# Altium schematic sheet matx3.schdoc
size 594 x 419 mm; Symbol: Drawing-Symbol_A4; @Project Name: Inverted_MAML_6x6; @Page Count: 1; @Update Date: 2026-06-14; @Create Date: 2026-06-14; @Schematic Name: Schematic1; @Page No: 1; @Page Name: P1; Company: EasyEDA.com; Version: V1.0; Page Size: A4; Device: Drawing-Symbol_A4; @Create Time: 14:27:06; @Update Time: 14:27:06; Border: 1; Width: 2338; Height: 1652; Region Start: 1; X Region Count: 6; Y Region Count: 4; Blade Width: 10; Title Block Position: 3
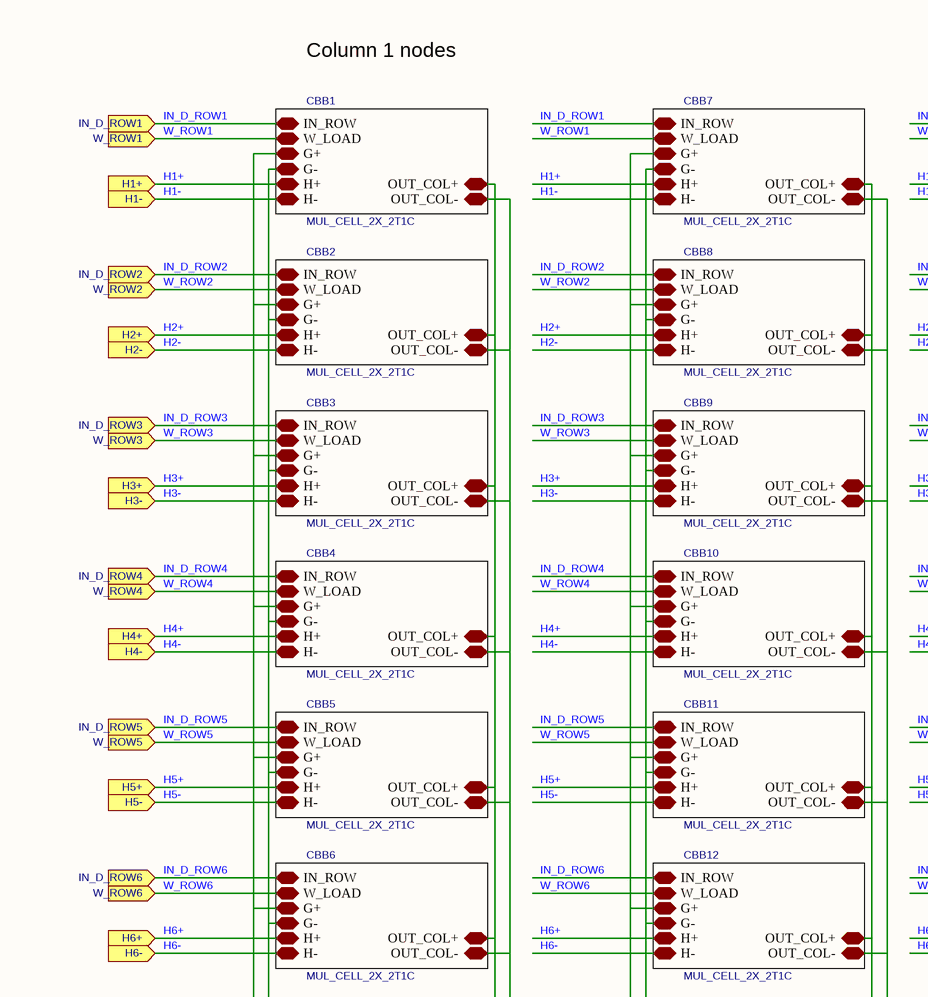
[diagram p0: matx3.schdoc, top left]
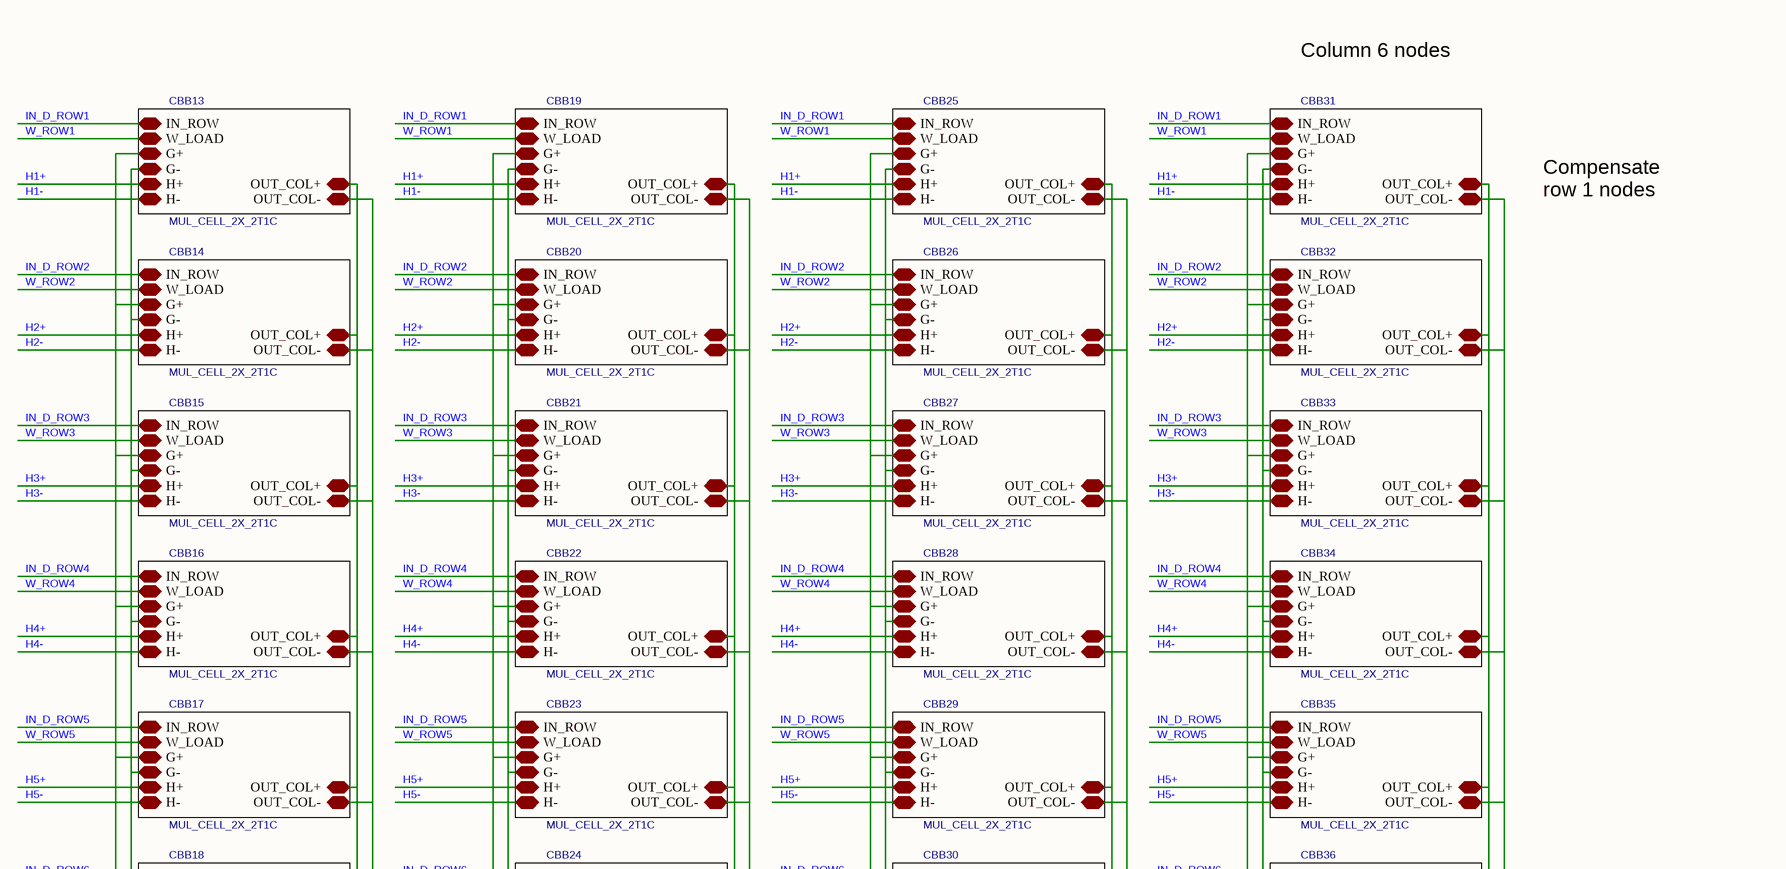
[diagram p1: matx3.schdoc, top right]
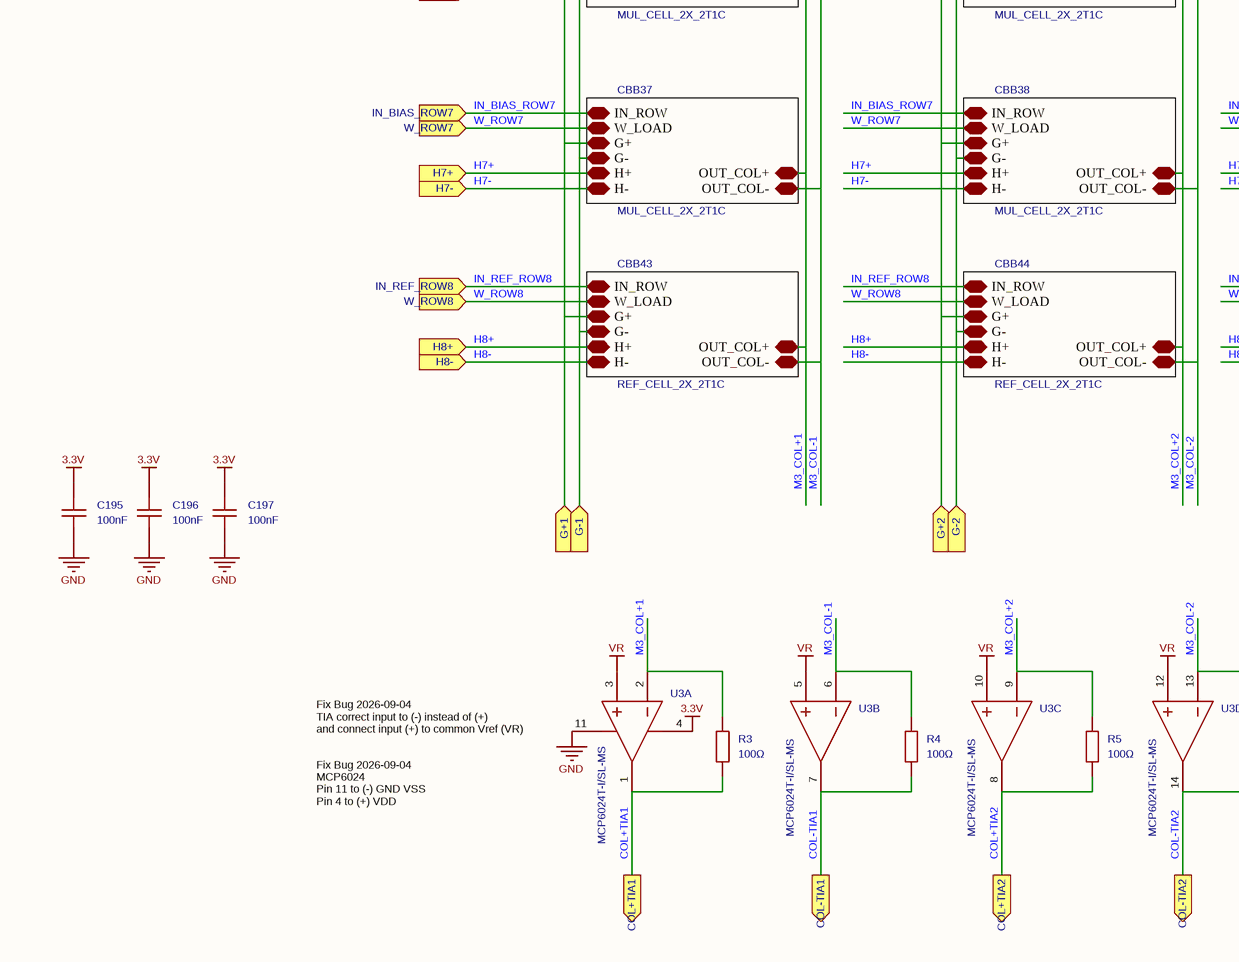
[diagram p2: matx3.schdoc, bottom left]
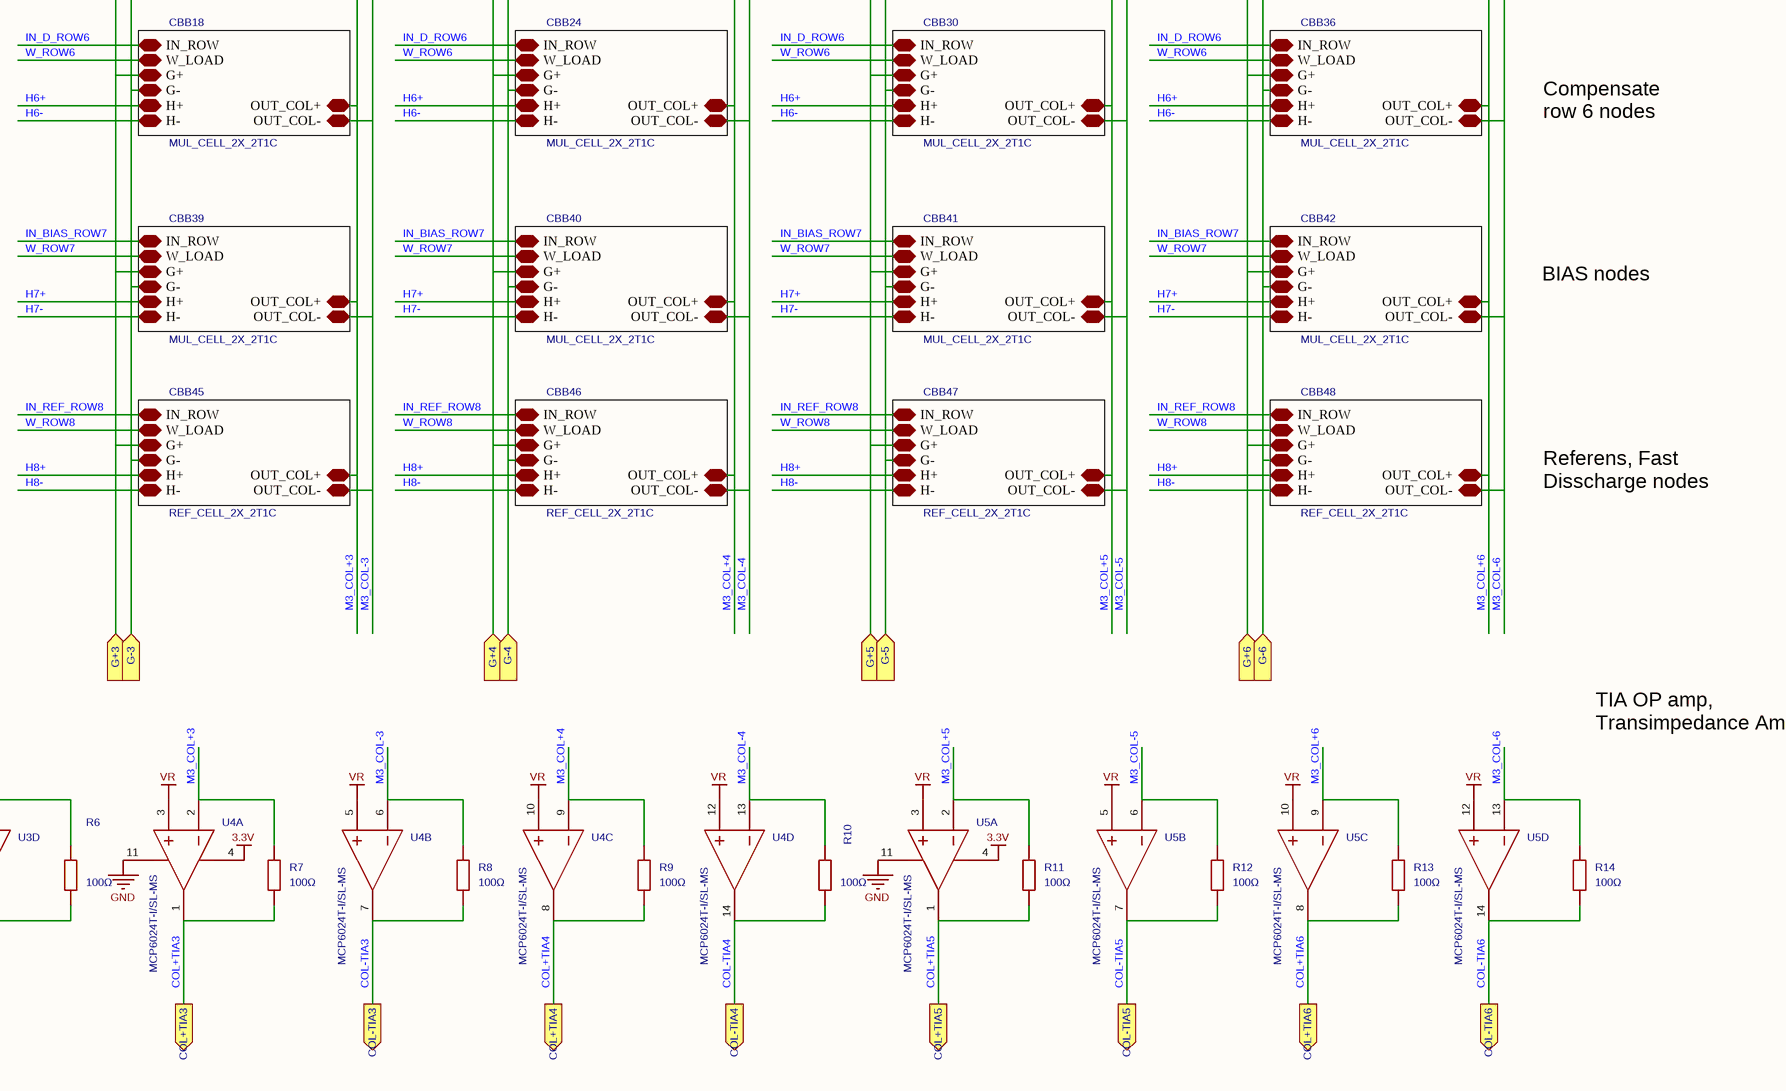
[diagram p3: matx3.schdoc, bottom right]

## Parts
C195  100nF  [C0402]
C196  100nF  [C0402]
C197  100nF  [C0402]
R3  100Ω  [R0402]
R4  100Ω  [R0402]
R5  100Ω  [R0402]
R6  100Ω  [R0402]
R7  100Ω  [R0402]
R8  100Ω  [R0402]
R9  100Ω  [R0402]
R10  100Ω  [R0402]
R11  100Ω  [R0402]
R12  100Ω  [R0402]
R13  100Ω  [R0402]
R14  100Ω  [R0402]
U3  MCP6024T-I/SL-MS  [SOIC-14_L8.7-W3.9-P1.27-LS6.0-BL-1]  (parts A,B,C,D of 4)
U4  MCP6024T-I/SL-MS  [SOIC-14_L8.7-W3.9-P1.27-LS6.0-BL-1]  (parts A,B,C,D of 4)
U5  MCP6024T-I/SL-MS  [SOIC-14_L8.7-W3.9-P1.27-LS6.0-BL-1]  (parts A,B,C,D of 4)

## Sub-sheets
CBB1 = MUL_CELL_2X_2T1C_matrix_3_8_MUL_CELL.schdoc: H+, G+, W_LOAD, IN_ROW, G-, H-, OUT_COL+, OUT_COL-  | Symbol: MUL_CELL_2X_2T1C
CBB2 = MUL_CELL_2X_2T1C_matrix_3_8_MUL_CELL.schdoc: H+, G+, W_LOAD, IN_ROW, G-, H-, OUT_COL+, OUT_COL-  | Symbol: MUL_CELL_2X_2T1C
CBB3 = MUL_CELL_2X_2T1C_matrix_3_8_MUL_CELL.schdoc: H+, G+, W_LOAD, IN_ROW, G-, H-, OUT_COL+, OUT_COL-  | Symbol: MUL_CELL_2X_2T1C
CBB4 = MUL_CELL_2X_2T1C_matrix_3_8_MUL_CELL.schdoc: H+, G+, W_LOAD, IN_ROW, G-, H-, OUT_COL+, OUT_COL-  | Symbol: MUL_CELL_2X_2T1C
CBB5 = MUL_CELL_2X_2T1C_matrix_3_8_MUL_CELL.schdoc: H+, G+, W_LOAD, IN_ROW, G-, H-, OUT_COL+, OUT_COL-  | Symbol: MUL_CELL_2X_2T1C
CBB6 = MUL_CELL_2X_2T1C_matrix_3_8_MUL_CELL.schdoc: H+, G+, W_LOAD, IN_ROW, G-, H-, OUT_COL+, OUT_COL-  | Symbol: MUL_CELL_2X_2T1C
CBB7 = MUL_CELL_2X_2T1C_matrix_3_8_MUL_CELL.schdoc: H+, G+, W_LOAD, IN_ROW, G-, H-, OUT_COL+, OUT_COL-  | Symbol: MUL_CELL_2X_2T1C
CBB8 = MUL_CELL_2X_2T1C_matrix_3_8_MUL_CELL.schdoc: H+, G+, W_LOAD, IN_ROW, G-, H-, OUT_COL+, OUT_COL-  | Symbol: MUL_CELL_2X_2T1C
CBB9 = MUL_CELL_2X_2T1C_matrix_3_8_MUL_CELL.schdoc: H+, G+, W_LOAD, IN_ROW, G-, H-, OUT_COL+, OUT_COL-  | Symbol: MUL_CELL_2X_2T1C
CBB10 = MUL_CELL_2X_2T1C_matrix_3_8_MUL_CELL.schdoc: H+, G+, W_LOAD, IN_ROW, G-, H-, OUT_COL+, OUT_COL-  | Symbol: MUL_CELL_2X_2T1C
CBB11 = MUL_CELL_2X_2T1C_matrix_3_8_MUL_CELL.schdoc: H+, G+, W_LOAD, IN_ROW, G-, H-, OUT_COL+, OUT_COL-  | Symbol: MUL_CELL_2X_2T1C
CBB12 = MUL_CELL_2X_2T1C_matrix_3_8_MUL_CELL.schdoc: H+, G+, W_LOAD, IN_ROW, G-, H-, OUT_COL+, OUT_COL-  | Symbol: MUL_CELL_2X_2T1C
CBB13 = MUL_CELL_2X_2T1C_matrix_3_8_MUL_CELL.schdoc: H+, G+, W_LOAD, IN_ROW, G-, H-, OUT_COL+, OUT_COL-  | Symbol: MUL_CELL_2X_2T1C
CBB14 = MUL_CELL_2X_2T1C_matrix_3_8_MUL_CELL.schdoc: H+, G+, W_LOAD, IN_ROW, G-, H-, OUT_COL+, OUT_COL-  | Symbol: MUL_CELL_2X_2T1C
CBB15 = MUL_CELL_2X_2T1C_matrix_3_8_MUL_CELL.schdoc: H+, G+, W_LOAD, IN_ROW, G-, H-, OUT_COL+, OUT_COL-  | Symbol: MUL_CELL_2X_2T1C
CBB16 = MUL_CELL_2X_2T1C_matrix_3_8_MUL_CELL.schdoc: H+, G+, W_LOAD, IN_ROW, G-, H-, OUT_COL+, OUT_COL-  | Symbol: MUL_CELL_2X_2T1C
CBB17 = MUL_CELL_2X_2T1C_matrix_3_8_MUL_CELL.schdoc: H+, G+, W_LOAD, IN_ROW, G-, H-, OUT_COL+, OUT_COL-  | Symbol: MUL_CELL_2X_2T1C
CBB18 = MUL_CELL_2X_2T1C_matrix_3_8_MUL_CELL.schdoc: H+, G+, W_LOAD, IN_ROW, G-, H-, OUT_COL+, OUT_COL-  | Symbol: MUL_CELL_2X_2T1C
CBB19 = MUL_CELL_2X_2T1C_matrix_3_8_MUL_CELL.schdoc: H+, G+, W_LOAD, IN_ROW, G-, H-, OUT_COL+, OUT_COL-  | Symbol: MUL_CELL_2X_2T1C
CBB20 = MUL_CELL_2X_2T1C_matrix_3_8_MUL_CELL.schdoc: H+, G+, W_LOAD, IN_ROW, G-, H-, OUT_COL+, OUT_COL-  | Symbol: MUL_CELL_2X_2T1C
CBB21 = MUL_CELL_2X_2T1C_matrix_3_8_MUL_CELL.schdoc: H+, G+, W_LOAD, IN_ROW, G-, H-, OUT_COL+, OUT_COL-  | Symbol: MUL_CELL_2X_2T1C
CBB22 = MUL_CELL_2X_2T1C_matrix_3_8_MUL_CELL.schdoc: H+, G+, W_LOAD, IN_ROW, G-, H-, OUT_COL+, OUT_COL-  | Symbol: MUL_CELL_2X_2T1C
CBB23 = MUL_CELL_2X_2T1C_matrix_3_8_MUL_CELL.schdoc: H+, G+, W_LOAD, IN_ROW, G-, H-, OUT_COL+, OUT_COL-  | Symbol: MUL_CELL_2X_2T1C
CBB24 = MUL_CELL_2X_2T1C_matrix_3_8_MUL_CELL.schdoc: H+, G+, W_LOAD, IN_ROW, G-, H-, OUT_COL+, OUT_COL-  | Symbol: MUL_CELL_2X_2T1C
CBB25 = MUL_CELL_2X_2T1C_matrix_3_8_MUL_CELL.schdoc: H+, G+, W_LOAD, IN_ROW, G-, H-, OUT_COL+, OUT_COL-  | Symbol: MUL_CELL_2X_2T1C
CBB26 = MUL_CELL_2X_2T1C_matrix_3_8_MUL_CELL.schdoc: H+, G+, W_LOAD, IN_ROW, G-, H-, OUT_COL+, OUT_COL-  | Symbol: MUL_CELL_2X_2T1C
CBB27 = MUL_CELL_2X_2T1C_matrix_3_8_MUL_CELL.schdoc: H+, G+, W_LOAD, IN_ROW, G-, H-, OUT_COL+, OUT_COL-  | Symbol: MUL_CELL_2X_2T1C
CBB28 = MUL_CELL_2X_2T1C_matrix_3_8_MUL_CELL.schdoc: H+, G+, W_LOAD, IN_ROW, G-, H-, OUT_COL+, OUT_COL-  | Symbol: MUL_CELL_2X_2T1C
CBB29 = MUL_CELL_2X_2T1C_matrix_3_8_MUL_CELL.schdoc: H+, G+, W_LOAD, IN_ROW, G-, H-, OUT_COL+, OUT_COL-  | Symbol: MUL_CELL_2X_2T1C
CBB30 = MUL_CELL_2X_2T1C_matrix_3_8_MUL_CELL.schdoc: H+, G+, W_LOAD, IN_ROW, G-, H-, OUT_COL+, OUT_COL-  | Symbol: MUL_CELL_2X_2T1C
CBB31 = MUL_CELL_2X_2T1C_matrix_3_8_MUL_CELL.schdoc: H+, G+, W_LOAD, IN_ROW, G-, H-, OUT_COL+, OUT_COL-  | Symbol: MUL_CELL_2X_2T1C
CBB32 = MUL_CELL_2X_2T1C_matrix_3_8_MUL_CELL.schdoc: H+, G+, W_LOAD, IN_ROW, G-, H-, OUT_COL+, OUT_COL-  | Symbol: MUL_CELL_2X_2T1C
CBB33 = MUL_CELL_2X_2T1C_matrix_3_8_MUL_CELL.schdoc: H+, G+, W_LOAD, IN_ROW, G-, H-, OUT_COL+, OUT_COL-  | Symbol: MUL_CELL_2X_2T1C
CBB34 = MUL_CELL_2X_2T1C_matrix_3_8_MUL_CELL.schdoc: H+, G+, W_LOAD, IN_ROW, G-, H-, OUT_COL+, OUT_COL-  | Symbol: MUL_CELL_2X_2T1C
CBB35 = MUL_CELL_2X_2T1C_matrix_3_8_MUL_CELL.schdoc: H+, G+, W_LOAD, IN_ROW, G-, H-, OUT_COL+, OUT_COL-  | Symbol: MUL_CELL_2X_2T1C
CBB36 = MUL_CELL_2X_2T1C_matrix_3_8_MUL_CELL.schdoc: H+, G+, W_LOAD, IN_ROW, G-, H-, OUT_COL+, OUT_COL-  | Symbol: MUL_CELL_2X_2T1C
CBB37 = MUL_CELL_2X_2T1C_matrix_3_8_MUL_CELL.schdoc: H+, G+, W_LOAD, IN_ROW, G-, H-, OUT_COL+, OUT_COL-  | Symbol: MUL_CELL_2X_2T1C
CBB38 = MUL_CELL_2X_2T1C_matrix_3_8_MUL_CELL.schdoc: H+, G+, W_LOAD, IN_ROW, G-, H-, OUT_COL+, OUT_COL-  | Symbol: MUL_CELL_2X_2T1C
CBB39 = MUL_CELL_2X_2T1C_matrix_3_8_MUL_CELL.schdoc: H+, G+, W_LOAD, IN_ROW, G-, H-, OUT_COL+, OUT_COL-  | Symbol: MUL_CELL_2X_2T1C
CBB40 = MUL_CELL_2X_2T1C_matrix_3_8_MUL_CELL.schdoc: H+, G+, W_LOAD, IN_ROW, G-, H-, OUT_COL+, OUT_COL-  | Symbol: MUL_CELL_2X_2T1C
CBB41 = MUL_CELL_2X_2T1C_matrix_3_8_MUL_CELL.schdoc: H+, G+, W_LOAD, IN_ROW, G-, H-, OUT_COL+, OUT_COL-  | Symbol: MUL_CELL_2X_2T1C
CBB42 = MUL_CELL_2X_2T1C_matrix_3_8_MUL_CELL.schdoc: H+, G+, W_LOAD, IN_ROW, G-, H-, OUT_COL+, OUT_COL-  | Symbol: MUL_CELL_2X_2T1C
CBB43 = matrix_3_REF_CELL.schdoc: H+, G+, W_LOAD, IN_ROW, G-, H-, OUT_COL+, OUT_COL-  | Symbol: REF_CELL_2X_2T1C
CBB44 = matrix_3_REF_CELL.schdoc: H+, G+, W_LOAD, IN_ROW, G-, H-, OUT_COL+, OUT_COL-  | Symbol: REF_CELL_2X_2T1C
CBB45 = matrix_3_REF_CELL.schdoc: H+, G+, W_LOAD, IN_ROW, G-, H-, OUT_COL+, OUT_COL-  | Symbol: REF_CELL_2X_2T1C
CBB46 = matrix_3_REF_CELL.schdoc: H+, G+, W_LOAD, IN_ROW, G-, H-, OUT_COL+, OUT_COL-  | Symbol: REF_CELL_2X_2T1C
CBB47 = matrix_3_REF_CELL.schdoc: H+, G+, W_LOAD, IN_ROW, G-, H-, OUT_COL+, OUT_COL-  | Symbol: REF_CELL_2X_2T1C
CBB48 = matrix_3_REF_CELL.schdoc: H+, G+, W_LOAD, IN_ROW, G-, H-, OUT_COL+, OUT_COL-  | Symbol: REF_CELL_2X_2T1C

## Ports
COL+TIA1 (out), COL+TIA2 (out), COL+TIA3 (out), COL+TIA4 (out), COL+TIA5 (out), COL+TIA6 (out), COL-TIA1 (out), COL-TIA2 (out), COL-TIA3 (out), COL-TIA4 (out), COL-TIA5 (out), COL-TIA6 (out), G+1 (in), G+2 (in), G+3 (in), G+4 (in), G+5 (in), G+6 (in), G-1 (in), G-2 (in), G-3 (in), G-4 (in), G-5 (in), G-6 (in), H1+ (in), H1- (in), H2+ (in), H2- (in), H3+ (in), H3- (in), H4+ (in), H4- (in), H5+ (in), H5- (in), H6+ (in), H6- (in), H7+ (in), H7- (in), H8+ (in), H8- (in), IN_BIAS_ROW7 (in), IN_D_ROW1 (in), IN_D_ROW2 (in), IN_D_ROW3 (in), IN_D_ROW4 (in), IN_D_ROW5 (in), IN_D_ROW6 (in), IN_REF_ROW8 (in), W_ROW1 (in), W_ROW2 (in), W_ROW3 (in), W_ROW4 (in), W_ROW5 (in), W_ROW6 (in), W_ROW7 (in), W_ROW8 (in)

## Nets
3.3V: C195.2 C196.2 C197.2 U3.4(V+) U4.4(V+) U5.4(V+)
GND: C195.1 C196.1 C197.1 U3.11(V-) U4.11(V-) U5.11(V-)
VR: U3.3(IN1+) U3.5(IN2+) U3.10(IN3+) U3.12(IN4+) U4.3(IN1+) U4.5(IN2+) U4.10(IN3+) U4.12(IN4+) U5.3(IN1+) U5.5(IN2+) U5.10(IN3+) U5.12(IN4+)
COL+TIA1: R3.1 U3.1(OUT1) ; port COL+TIA1
COL+TIA2: R5.1 U3.8(OUT3) ; port COL+TIA2
COL+TIA3: R7.1 U4.1(OUT1) ; port COL+TIA3
COL+TIA4: R9.1 U4.8(OUT3) ; port COL+TIA4
COL+TIA5: R11.1 U5.1(OUT1) ; port COL+TIA5
COL+TIA6: R13.1 U5.8(OUT3) ; port COL+TIA6
COL-TIA1: R4.1 U3.7(OUT2) ; port COL-TIA1
COL-TIA2: R6.1 U3.14(OUT4) ; port COL-TIA2
COL-TIA3: R8.1 U4.7(OUT2) ; port COL-TIA3
COL-TIA4: R10.1 U4.14(OUT4) ; port COL-TIA4
COL-TIA5: R12.1 U5.7(OUT2) ; port COL-TIA5
COL-TIA6: R14.1 U5.14(OUT4) ; port COL-TIA6
G+1: port G+1, sheet CBB1/G+, sheet CBB2/G+, sheet CBB3/G+, sheet CBB4/G+, sheet CBB5/G+, sheet CBB6/G+, sheet CBB37/G+, sheet CBB43/G+
G+2: port G+2, sheet CBB7/G+, sheet CBB8/G+, sheet CBB9/G+, sheet CBB10/G+, sheet CBB11/G+, sheet CBB12/G+, sheet CBB38/G+, sheet CBB44/G+
G+3: port G+3, sheet CBB13/G+, sheet CBB14/G+, sheet CBB15/G+, sheet CBB16/G+, sheet CBB17/G+, sheet CBB18/G+, sheet CBB39/G+, sheet CBB45/G+
G+4: port G+4, sheet CBB19/G+, sheet CBB20/G+, sheet CBB21/G+, sheet CBB22/G+, sheet CBB23/G+, sheet CBB24/G+, sheet CBB40/G+, sheet CBB46/G+
G+5: port G+5, sheet CBB25/G+, sheet CBB26/G+, sheet CBB27/G+, sheet CBB28/G+, sheet CBB29/G+, sheet CBB30/G+, sheet CBB41/G+, sheet CBB47/G+
G+6: port G+6, sheet CBB31/G+, sheet CBB32/G+, sheet CBB33/G+, sheet CBB34/G+, sheet CBB35/G+, sheet CBB36/G+, sheet CBB42/G+, sheet CBB48/G+
G-1: port G-1, sheet CBB1/G-, sheet CBB2/G-, sheet CBB3/G-, sheet CBB4/G-, sheet CBB5/G-, sheet CBB6/G-, sheet CBB37/G-, sheet CBB43/G-
G-2: port G-2, sheet CBB7/G-, sheet CBB8/G-, sheet CBB9/G-, sheet CBB10/G-, sheet CBB11/G-, sheet CBB12/G-, sheet CBB38/G-, sheet CBB44/G-
G-3: port G-3, sheet CBB13/G-, sheet CBB14/G-, sheet CBB15/G-, sheet CBB16/G-, sheet CBB17/G-, sheet CBB18/G-, sheet CBB39/G-, sheet CBB45/G-
G-4: port G-4, sheet CBB19/G-, sheet CBB20/G-, sheet CBB21/G-, sheet CBB22/G-, sheet CBB23/G-, sheet CBB24/G-, sheet CBB40/G-, sheet CBB46/G-
G-5: port G-5, sheet CBB25/G-, sheet CBB26/G-, sheet CBB27/G-, sheet CBB28/G-, sheet CBB29/G-, sheet CBB30/G-, sheet CBB41/G-, sheet CBB47/G-
G-6: port G-6, sheet CBB31/G-, sheet CBB32/G-, sheet CBB33/G-, sheet CBB34/G-, sheet CBB35/G-, sheet CBB36/G-, sheet CBB42/G-, sheet CBB48/G-
H1+: port H1+, sheet CBB1/H+, sheet CBB7/H+, sheet CBB13/H+, sheet CBB19/H+, sheet CBB25/H+, sheet CBB31/H+
H1-: port H1-, sheet CBB1/H-, sheet CBB7/H-, sheet CBB13/H-, sheet CBB19/H-, sheet CBB25/H-, sheet CBB31/H-
H2+: port H2+, sheet CBB2/H+, sheet CBB8/H+, sheet CBB14/H+, sheet CBB20/H+, sheet CBB26/H+, sheet CBB32/H+
H2-: port H2-, sheet CBB2/H-, sheet CBB8/H-, sheet CBB14/H-, sheet CBB20/H-, sheet CBB26/H-, sheet CBB32/H-
H3+: port H3+, sheet CBB3/H+, sheet CBB9/H+, sheet CBB15/H+, sheet CBB21/H+, sheet CBB27/H+, sheet CBB33/H+
H3-: port H3-, sheet CBB3/H-, sheet CBB9/H-, sheet CBB15/H-, sheet CBB21/H-, sheet CBB27/H-, sheet CBB33/H-
H4+: port H4+, sheet CBB4/H+, sheet CBB10/H+, sheet CBB16/H+, sheet CBB22/H+, sheet CBB28/H+, sheet CBB34/H+
H4-: port H4-, sheet CBB4/H-, sheet CBB10/H-, sheet CBB16/H-, sheet CBB22/H-, sheet CBB28/H-, sheet CBB34/H-
H5+: port H5+, sheet CBB5/H+, sheet CBB11/H+, sheet CBB17/H+, sheet CBB23/H+, sheet CBB29/H+, sheet CBB35/H+
H5-: port H5-, sheet CBB5/H-, sheet CBB11/H-, sheet CBB17/H-, sheet CBB23/H-, sheet CBB29/H-, sheet CBB35/H-
H6+: port H6+, sheet CBB6/H+, sheet CBB12/H+, sheet CBB18/H+, sheet CBB24/H+, sheet CBB30/H+, sheet CBB36/H+
H6-: port H6-, sheet CBB6/H-, sheet CBB12/H-, sheet CBB18/H-, sheet CBB24/H-, sheet CBB30/H-, sheet CBB36/H-
H7+: port H7+, sheet CBB37/H+, sheet CBB38/H+, sheet CBB39/H+, sheet CBB40/H+, sheet CBB41/H+, sheet CBB42/H+
H7-: port H7-, sheet CBB37/H-, sheet CBB38/H-, sheet CBB39/H-, sheet CBB40/H-, sheet CBB41/H-, sheet CBB42/H-
H8+: port H8+, sheet CBB43/H+, sheet CBB44/H+, sheet CBB45/H+, sheet CBB46/H+, sheet CBB47/H+, sheet CBB48/H+
H8-: port H8-, sheet CBB43/H-, sheet CBB44/H-, sheet CBB45/H-, sheet CBB46/H-, sheet CBB47/H-, sheet CBB48/H-
IN_BIAS_ROW7: port IN_BIAS_ROW7, sheet CBB37/IN_ROW, sheet CBB38/IN_ROW, sheet CBB39/IN_ROW, sheet CBB40/IN_ROW, sheet CBB41/IN_ROW, sheet CBB42/IN_ROW
IN_D_ROW1: port IN_D_ROW1, sheet CBB1/IN_ROW, sheet CBB7/IN_ROW, sheet CBB13/IN_ROW, sheet CBB19/IN_ROW, sheet CBB25/IN_ROW, sheet CBB31/IN_ROW
IN_D_ROW2: port IN_D_ROW2, sheet CBB2/IN_ROW, sheet CBB8/IN_ROW, sheet CBB14/IN_ROW, sheet CBB20/IN_ROW, sheet CBB26/IN_ROW, sheet CBB32/IN_ROW
IN_D_ROW3: port IN_D_ROW3, sheet CBB3/IN_ROW, sheet CBB9/IN_ROW, sheet CBB15/IN_ROW, sheet CBB21/IN_ROW, sheet CBB27/IN_ROW, sheet CBB33/IN_ROW
IN_D_ROW4: port IN_D_ROW4, sheet CBB4/IN_ROW, sheet CBB10/IN_ROW, sheet CBB16/IN_ROW, sheet CBB22/IN_ROW, sheet CBB28/IN_ROW, sheet CBB34/IN_ROW
IN_D_ROW5: port IN_D_ROW5, sheet CBB5/IN_ROW, sheet CBB11/IN_ROW, sheet CBB17/IN_ROW, sheet CBB23/IN_ROW, sheet CBB29/IN_ROW, sheet CBB35/IN_ROW
IN_D_ROW6: port IN_D_ROW6, sheet CBB6/IN_ROW, sheet CBB12/IN_ROW, sheet CBB18/IN_ROW, sheet CBB24/IN_ROW, sheet CBB30/IN_ROW, sheet CBB36/IN_ROW
IN_REF_ROW8: port IN_REF_ROW8, sheet CBB43/IN_ROW, sheet CBB44/IN_ROW, sheet CBB45/IN_ROW, sheet CBB46/IN_ROW, sheet CBB47/IN_ROW, sheet CBB48/IN_ROW
M3_COL+1: R3.2 U3.2(IN1-) ; sheet CBB1/OUT_COL+, sheet CBB2/OUT_COL+, sheet CBB3/OUT_COL+, sheet CBB4/OUT_COL+, sheet CBB5/OUT_COL+, sheet CBB6/OUT_COL+, sheet CBB37/OUT_COL+, sheet CBB43/OUT_COL+
M3_COL+2: R5.2 U3.9(IN3-) ; sheet CBB7/OUT_COL+, sheet CBB8/OUT_COL+, sheet CBB9/OUT_COL+, sheet CBB10/OUT_COL+, sheet CBB11/OUT_COL+, sheet CBB12/OUT_COL+, sheet CBB38/OUT_COL+, sheet CBB44/OUT_COL+
M3_COL+3: R7.2 U4.2(IN1-) ; sheet CBB13/OUT_COL+, sheet CBB14/OUT_COL+, sheet CBB15/OUT_COL+, sheet CBB16/OUT_COL+, sheet CBB17/OUT_COL+, sheet CBB18/OUT_COL+, sheet CBB39/OUT_COL+, sheet CBB45/OUT_COL+
M3_COL+4: R9.2 U4.9(IN3-) ; sheet CBB19/OUT_COL+, sheet CBB20/OUT_COL+, sheet CBB21/OUT_COL+, sheet CBB22/OUT_COL+, sheet CBB23/OUT_COL+, sheet CBB24/OUT_COL+, sheet CBB40/OUT_COL+, sheet CBB46/OUT_COL+
M3_COL+5: R11.2 U5.2(IN1-) ; sheet CBB25/OUT_COL+, sheet CBB26/OUT_COL+, sheet CBB27/OUT_COL+, sheet CBB28/OUT_COL+, sheet CBB29/OUT_COL+, sheet CBB30/OUT_COL+, sheet CBB41/OUT_COL+, sheet CBB47/OUT_COL+
M3_COL+6: R13.2 U5.9(IN3-) ; sheet CBB31/OUT_COL+, sheet CBB32/OUT_COL+, sheet CBB33/OUT_COL+, sheet CBB34/OUT_COL+, sheet CBB35/OUT_COL+, sheet CBB36/OUT_COL+, sheet CBB42/OUT_COL+, sheet CBB48/OUT_COL+
M3_COL-1: R4.2 U3.6(IN2-) ; sheet CBB1/OUT_COL-, sheet CBB2/OUT_COL-, sheet CBB3/OUT_COL-, sheet CBB4/OUT_COL-, sheet CBB5/OUT_COL-, sheet CBB6/OUT_COL-, sheet CBB37/OUT_COL-, sheet CBB43/OUT_COL-
M3_COL-2: R6.2 U3.13(IN4-) ; sheet CBB7/OUT_COL-, sheet CBB8/OUT_COL-, sheet CBB9/OUT_COL-, sheet CBB10/OUT_COL-, sheet CBB11/OUT_COL-, sheet CBB12/OUT_COL-, sheet CBB38/OUT_COL-, sheet CBB44/OUT_COL-
M3_COL-3: R8.2 U4.6(IN2-) ; sheet CBB13/OUT_COL-, sheet CBB14/OUT_COL-, sheet CBB15/OUT_COL-, sheet CBB16/OUT_COL-, sheet CBB17/OUT_COL-, sheet CBB18/OUT_COL-, sheet CBB39/OUT_COL-, sheet CBB45/OUT_COL-
M3_COL-4: R10.2 U4.13(IN4-) ; sheet CBB19/OUT_COL-, sheet CBB20/OUT_COL-, sheet CBB21/OUT_COL-, sheet CBB22/OUT_COL-, sheet CBB23/OUT_COL-, sheet CBB24/OUT_COL-, sheet CBB40/OUT_COL-, sheet CBB46/OUT_COL-
M3_COL-5: R12.2 U5.6(IN2-) ; sheet CBB25/OUT_COL-, sheet CBB26/OUT_COL-, sheet CBB27/OUT_COL-, sheet CBB28/OUT_COL-, sheet CBB29/OUT_COL-, sheet CBB30/OUT_COL-, sheet CBB41/OUT_COL-, sheet CBB47/OUT_COL-
M3_COL-6: R14.2 U5.13(IN4-) ; sheet CBB31/OUT_COL-, sheet CBB32/OUT_COL-, sheet CBB33/OUT_COL-, sheet CBB34/OUT_COL-, sheet CBB35/OUT_COL-, sheet CBB36/OUT_COL-, sheet CBB42/OUT_COL-, sheet CBB48/OUT_COL-
W_ROW1: port W_ROW1, sheet CBB1/W_LOAD, sheet CBB7/W_LOAD, sheet CBB13/W_LOAD, sheet CBB19/W_LOAD, sheet CBB25/W_LOAD, sheet CBB31/W_LOAD
W_ROW2: port W_ROW2, sheet CBB2/W_LOAD, sheet CBB8/W_LOAD, sheet CBB14/W_LOAD, sheet CBB20/W_LOAD, sheet CBB26/W_LOAD, sheet CBB32/W_LOAD
W_ROW3: port W_ROW3, sheet CBB3/W_LOAD, sheet CBB9/W_LOAD, sheet CBB15/W_LOAD, sheet CBB21/W_LOAD, sheet CBB27/W_LOAD, sheet CBB33/W_LOAD
W_ROW4: port W_ROW4, sheet CBB4/W_LOAD, sheet CBB10/W_LOAD, sheet CBB16/W_LOAD, sheet CBB22/W_LOAD, sheet CBB28/W_LOAD, sheet CBB34/W_LOAD
W_ROW5: port W_ROW5, sheet CBB5/W_LOAD, sheet CBB11/W_LOAD, sheet CBB17/W_LOAD, sheet CBB23/W_LOAD, sheet CBB29/W_LOAD, sheet CBB35/W_LOAD
W_ROW6: port W_ROW6, sheet CBB6/W_LOAD, sheet CBB12/W_LOAD, sheet CBB18/W_LOAD, sheet CBB24/W_LOAD, sheet CBB30/W_LOAD, sheet CBB36/W_LOAD
W_ROW7: port W_ROW7, sheet CBB37/W_LOAD, sheet CBB38/W_LOAD, sheet CBB39/W_LOAD, sheet CBB40/W_LOAD, sheet CBB41/W_LOAD, sheet CBB42/W_LOAD
W_ROW8: port W_ROW8, sheet CBB43/W_LOAD, sheet CBB44/W_LOAD, sheet CBB45/W_LOAD, sheet CBB46/W_LOAD, sheet CBB47/W_LOAD, sheet CBB48/W_LOAD

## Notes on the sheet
- Column 1 nodes
- Column 6 nodes
- Compensate
  row 1 nodes
- Compensate
  row 6 nodes
- BIAS nodes
- Referens, Fast
  Disscharge nodes
- (near R14) TIA OP amp,
  Transimpedance Amplifier
- Fix Bug 2026-09-04
  TIA correct input to (-) instead of (+)
  and connect input (+) to common Vref (VR)
- Fix Bug 2026-09-04
  MCP6024
  Pin 11 to (-) GND VSS
  Pin 4 to (+) VDD

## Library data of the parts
C195-C197 = CL05B104KO5NNNC: Capacitance:100nF Tolerance:±10% Tolerance:±10% Voltage Rating:16V Temperature Coefficient:X7R; Manufacturer: SAMSUNG(三星); 3D Model: b7d13df3e9464d7a99d0651d1a5b4d570819f05c4eef4c71ace90d822a990e87; 3D Model Transform: 39.37,19.685,0,0,0,0,0,0,0; Tolerance: ±10%; Voltage Rating: 16V; Temperature Coefficient: X7R; AddInBom: yes; ModelName: C0402_L1.0-W0.5-H0.5
R3-R14 = 0402WGF1000TCE: Type:Thick Film Resistors Resistance: Tolerance:±1% Tolerance:±1% Power(Watts): Overload Voltage (Max): Temperature Coefficient:±200ppm/℃ Temperature Coefficient:±200ppm/℃ Operating Temperature Range:-55℃~+155℃ Operating Temperature Range:-55℃~+155℃; Manufacturer: UNI-ROYAL(厚声); 3D Model: efdecb7dae4442949d28eecaf748420f0819f05c4eef4c71ace90d822a990e87; 3D Model Transform: 39.37,19.685,0,0,0,0,0,0,0; Tolerance: ±1%; AddInBom: yes; ModelName: R0402_L1.0-W0.5-H0.4
U3-U5 = MCP6024T-I/SL-MS: Manufacturer: MSKSEMI(美森科); Relevance: []; AddInBom: yes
